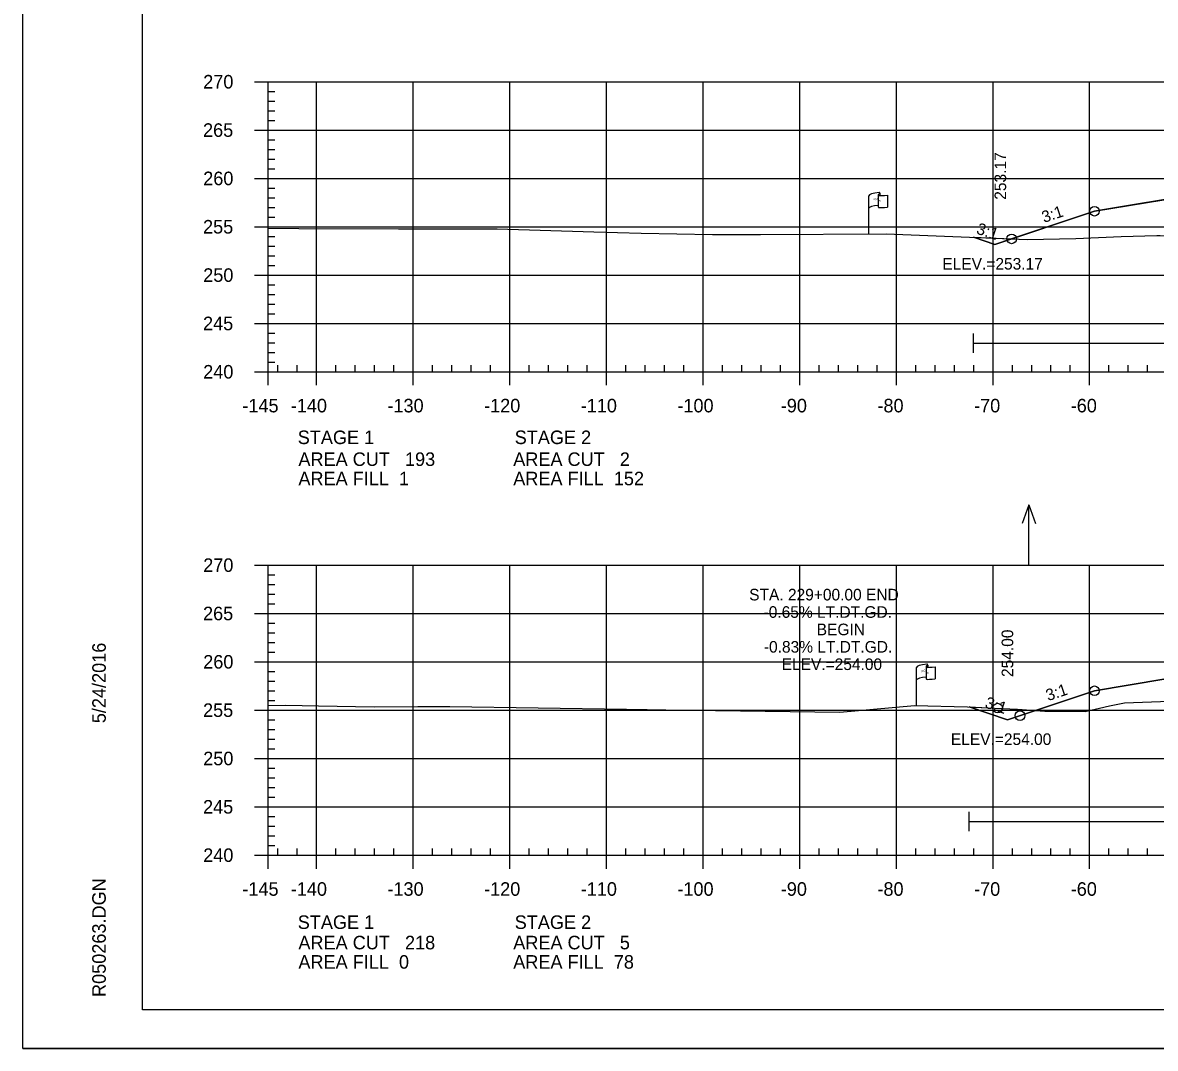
# Model space of a CAD drawing. Extents: x 1365647 to 1367999, y 387113 to 400173.
# Drawn here: x 1365723.7 to 1365840.9, y 392066.2 to 392172.3 of the extents above; entities that cross this region are included whole.
import ezdxf

# ---------------------------------------------------------------- set-up
doc = ezdxf.new("R2010")
doc.units = 0
for name, color, linetype in [('E_Existing ROW', 7, 'Continuous'), ('R_Axis', 7, 'Continuous'), ('R_Axis Annot', 7, 'Continuous'), ('R_Border', 7, 'Continuous'), ('R_Border Notes', 7, 'Continuous'), ('R_Contours', 7, 'Continuous'), ('R_Exist Surface', 7, 'Continuous'), ('R_Fin Surface', 7, 'Continuous'), ('R_Fin Surface Annot', 7, 'Continuous'), ('R_Grid', 7, 'Continuous'), ('R_No Plot', 7, 'Continuous'), ('R_Proposed Const Limits', 7, 'Continuous'), ('R_Water', 7, 'Continuous'), ('R_Water Annot', 7, 'Continuous')]:
    doc.layers.add(name, color=color, linetype=linetype)

msp = doc.modelspace()

# ---------------------------------------------------------------- linework, layer by layer
at = {"layer": 'E_Existing ROW'}
for p, q in [((1365811.23, 392150.41), (1365811.23, 392154.36)), ((1365812.22, 392154.45), (1365812.22, 392154.44)), ((1365812.22, 392154.44), (1365812.22, 392153.21)), ((1365812.39, 392154.61), (1365812.39, 392154.37)), ((1365813.16, 392154.41), (1365813.16, 392153.17)), ((1365817.17, 392105.66), (1365817.17, 392105.65)), ((1365817.17, 392105.65), (1365817.17, 392104.42)), ((1365817.34, 392105.82), (1365817.34, 392105.58)), ((1365818.1, 392105.62), (1365818.1, 392104.38)), ((1365816.17, 392101.62), (1365816.17, 392105.57))]:
    msp.add_line(p, q, dxfattribs=at)
for centre, radius, start, end in [((1365812.3, 392154.45), 0.078, 88.6458, 274.2828), ((1365812.31, 392154.61), 0.0783, 263.0712, 93.9564), ((1365812.3, 392153.21), 0.0783, 180, 273.9564), ((1365817.25, 392105.66), 0.078, 88.6458, 274.2828), ((1365817.26, 392105.82), 0.0783, 263.0712, 93.9564), ((1365817.25, 392104.42), 0.0783, 180, 273.9564)]:
    msp.add_arc(centre, radius, start, end, dxfattribs=at)
for centre, major_axis, ratio, start_param, end_param in [((1365812.81, 392154.4), (-1.58, -0.04), 0.19887, 5.030368, 6.283185), ((1365813.52, 392154.52), (-1.23, -0.13), 0.052933, 0.159456, 1.268315), ((1365812.8, 392153.08), (-1.58, -0.04), 0.19887, 5.083035, 6.194897), ((1365813.52, 392153.28), (-1.23, -0.13), 0.052933, 0.159456, 1.268315), ((1365817.75, 392105.61), (-1.58, -0.04), 0.19887, 5.030368, 6.283185), ((1365818.46, 392105.72), (-1.23, -0.13), 0.052933, 0.159456, 1.268315), ((1365817.75, 392104.29), (-1.58, -0.04), 0.19887, 5.083035, 6.194897), ((1365818.46, 392104.48), (-1.23, -0.13), 0.052933, 0.159456, 1.268315)]:
    msp.add_ellipse(centre, major_axis=major_axis, ratio=ratio, start_param=start_param, end_param=end_param, dxfattribs=at)
at = {"layer": 'R_Axis'}
for p, q in [((1365747.69, 392166.15), (1365749.09, 392166.15)), ((1365749.09, 392136.15), (1365749.09, 392166.15)), ((1365749.09, 392165.15), (1365749.79, 392165.15)), ((1365749.09, 392164.15), (1365749.79, 392164.15)), ((1365749.09, 392163.15), (1365749.79, 392163.15)), ((1365749.09, 392162.15), (1365749.79, 392162.15)), ((1365747.69, 392161.15), (1365749.09, 392161.15)), ((1365749.09, 392160.15), (1365749.79, 392160.15)), ((1365749.09, 392159.15), (1365749.79, 392159.15)), ((1365749.09, 392158.15), (1365749.79, 392158.15)), ((1365747.69, 392156.15), (1365749.09, 392156.15)), ((1365749.09, 392157.15), (1365749.79, 392157.15)), ((1365749.09, 392155.15), (1365749.79, 392155.15)), ((1365749.09, 392154.15), (1365749.79, 392154.15)), ((1365749.09, 392153.15), (1365749.79, 392153.15)), ((1365749.09, 392152.15), (1365749.79, 392152.15)), ((1365747.69, 392151.15), (1365749.09, 392151.15)), ((1365749.09, 392150.15), (1365749.79, 392150.15)), ((1365749.09, 392149.15), (1365749.79, 392149.15)), ((1365749.09, 392148.15), (1365749.79, 392148.15)), ((1365749.09, 392147.15), (1365749.79, 392147.15)), ((1365747.69, 392146.15), (1365749.09, 392146.15)), ((1365749.09, 392145.15), (1365749.79, 392145.15)), ((1365749.09, 392144.15), (1365749.79, 392144.15)), ((1365749.09, 392143.15), (1365749.79, 392143.15)), ((1365749.09, 392142.15), (1365749.79, 392142.15)), ((1365747.69, 392141.15), (1365749.09, 392141.15)), ((1365749.09, 392140.15), (1365749.79, 392140.15)), ((1365749.09, 392139.15), (1365749.79, 392139.15)), ((1365749.09, 392138.15), (1365749.79, 392138.15)), ((1365747.69, 392136.15), (1365749.09, 392136.15)), ((1365749.09, 392137.15), (1365749.79, 392137.15)), ((1365749.09, 392136.15), (1365749.09, 392136.85)), ((1365749.09, 392136.15), (1366039.09, 392136.15)), ((1365749.09, 392134.75), (1365749.09, 392136.15)), ((1365750.09, 392136.15), (1365750.09, 392136.85)), ((1365752.09, 392136.15), (1365752.09, 392136.85)), ((1365754.09, 392134.75), (1365754.09, 392136.15)), ((1365756.09, 392136.15), (1365756.09, 392136.85)), ((1365758.09, 392136.15), (1365758.09, 392136.85)), ((1365760.09, 392136.15), (1365760.09, 392136.85)), ((1365762.09, 392136.15), (1365762.09, 392136.85)), ((1365764.09, 392134.75), (1365764.09, 392136.15)), ((1365766.09, 392136.15), (1365766.09, 392136.85)), ((1365768.09, 392136.15), (1365768.09, 392136.85)), ((1365770.09, 392136.15), (1365770.09, 392136.85)), ((1365772.09, 392136.15), (1365772.09, 392136.85)), ((1365774.09, 392134.75), (1365774.09, 392136.15)), ((1365776.09, 392136.15), (1365776.09, 392136.85)), ((1365778.09, 392136.15), (1365778.09, 392136.85)), ((1365780.09, 392136.15), (1365780.09, 392136.85)), ((1365782.09, 392136.15), (1365782.09, 392136.85)), ((1365784.09, 392134.75), (1365784.09, 392136.15)), ((1365786.09, 392136.15), (1365786.09, 392136.85)), ((1365788.09, 392136.15), (1365788.09, 392136.85)), ((1365790.09, 392136.15), (1365790.09, 392136.85)), ((1365792.09, 392136.15), (1365792.09, 392136.85)), ((1365794.09, 392134.75), (1365794.09, 392136.15)), ((1365796.09, 392136.15), (1365796.09, 392136.85)), ((1365798.09, 392136.15), (1365798.09, 392136.85)), ((1365800.09, 392136.15), (1365800.09, 392136.85)), ((1365802.09, 392136.15), (1365802.09, 392136.85)), ((1365804.09, 392134.75), (1365804.09, 392136.15)), ((1365806.09, 392136.15), (1365806.09, 392136.85)), ((1365808.09, 392136.15), (1365808.09, 392136.85)), ((1365810.09, 392136.15), (1365810.09, 392136.85)), ((1365812.09, 392136.15), (1365812.09, 392136.85)), ((1365814.09, 392134.75), (1365814.09, 392136.15)), ((1365816.09, 392136.15), (1365816.09, 392136.85)), ((1365818.09, 392136.15), (1365818.09, 392136.85)), ((1365820.09, 392136.15), (1365820.09, 392136.85)), ((1365822.09, 392136.15), (1365822.09, 392136.85)), ((1365824.09, 392134.75), (1365824.09, 392136.15)), ((1365826.09, 392136.15), (1365826.09, 392136.85)), ((1365828.09, 392136.15), (1365828.09, 392136.85)), ((1365830.09, 392136.15), (1365830.09, 392136.85)), ((1365832.09, 392136.15), (1365832.09, 392136.85)), ((1365834.09, 392134.75), (1365834.09, 392136.15)), ((1365836.09, 392136.15), (1365836.09, 392136.85)), ((1365838.09, 392136.15), (1365838.09, 392136.85)), ((1365840.09, 392136.15), (1365840.09, 392136.85)), ((1365747.69, 392116.15), (1365749.09, 392116.15)), ((1365749.09, 392086.15), (1365749.09, 392116.15)), ((1365749.09, 392115.15), (1365749.79, 392115.15)), ((1365749.09, 392114.15), (1365749.79, 392114.15)), ((1365749.09, 392113.15), (1365749.79, 392113.15)), ((1365749.09, 392112.15), (1365749.79, 392112.15)), ((1365747.69, 392111.15), (1365749.09, 392111.15)), ((1365749.09, 392110.15), (1365749.79, 392110.15)), ((1365749.09, 392109.15), (1365749.79, 392109.15)), ((1365749.09, 392108.15), (1365749.79, 392108.15)), ((1365749.09, 392107.15), (1365749.79, 392107.15)), ((1365747.69, 392106.15), (1365749.09, 392106.15)), ((1365749.09, 392105.15), (1365749.79, 392105.15)), ((1365749.09, 392104.15), (1365749.79, 392104.15)), ((1365749.09, 392103.15), (1365749.79, 392103.15)), ((1365749.09, 392102.15), (1365749.79, 392102.15)), ((1365747.69, 392101.15), (1365749.09, 392101.15)), ((1365749.09, 392100.15), (1365749.79, 392100.15)), ((1365749.09, 392099.15), (1365749.79, 392099.15)), ((1365749.09, 392098.15), (1365749.79, 392098.15)), ((1365749.09, 392097.15), (1365749.79, 392097.15)), ((1365747.69, 392096.15), (1365749.09, 392096.15)), ((1365749.09, 392095.15), (1365749.79, 392095.15)), ((1365749.09, 392094.15), (1365749.79, 392094.15)), ((1365749.09, 392093.15), (1365749.79, 392093.15)), ((1365749.09, 392092.15), (1365749.79, 392092.15)), ((1365747.69, 392091.15), (1365749.09, 392091.15)), ((1365749.09, 392090.15), (1365749.79, 392090.15)), ((1365749.09, 392089.15), (1365749.79, 392089.15)), ((1365749.09, 392088.15), (1365749.79, 392088.15)), ((1365749.09, 392087.15), (1365749.79, 392087.15)), ((1365749.09, 392086.15), (1365749.09, 392086.85)), ((1365750.09, 392086.15), (1365750.09, 392086.85)), ((1365752.09, 392086.15), (1365752.09, 392086.85)), ((1365756.09, 392086.15), (1365756.09, 392086.85)), ((1365758.09, 392086.15), (1365758.09, 392086.85)), ((1365760.09, 392086.15), (1365760.09, 392086.85)), ((1365762.09, 392086.15), (1365762.09, 392086.85)), ((1365766.09, 392086.15), (1365766.09, 392086.85)), ((1365768.09, 392086.15), (1365768.09, 392086.85)), ((1365770.09, 392086.15), (1365770.09, 392086.85)), ((1365772.09, 392086.15), (1365772.09, 392086.85)), ((1365776.09, 392086.15), (1365776.09, 392086.85)), ((1365778.09, 392086.15), (1365778.09, 392086.85)), ((1365780.09, 392086.15), (1365780.09, 392086.85)), ((1365782.09, 392086.15), (1365782.09, 392086.85)), ((1365786.09, 392086.15), (1365786.09, 392086.85)), ((1365788.09, 392086.15), (1365788.09, 392086.85)), ((1365790.09, 392086.15), (1365790.09, 392086.85)), ((1365792.09, 392086.15), (1365792.09, 392086.85)), ((1365796.09, 392086.15), (1365796.09, 392086.85)), ((1365798.09, 392086.15), (1365798.09, 392086.85)), ((1365800.09, 392086.15), (1365800.09, 392086.85)), ((1365802.09, 392086.15), (1365802.09, 392086.85)), ((1365806.09, 392086.15), (1365806.09, 392086.85)), ((1365808.09, 392086.15), (1365808.09, 392086.85)), ((1365810.09, 392086.15), (1365810.09, 392086.85)), ((1365812.09, 392086.15), (1365812.09, 392086.85)), ((1365816.09, 392086.15), (1365816.09, 392086.85)), ((1365818.09, 392086.15), (1365818.09, 392086.85)), ((1365820.09, 392086.15), (1365820.09, 392086.85)), ((1365822.09, 392086.15), (1365822.09, 392086.85)), ((1365826.09, 392086.15), (1365826.09, 392086.85)), ((1365828.09, 392086.15), (1365828.09, 392086.85)), ((1365830.09, 392086.15), (1365830.09, 392086.85)), ((1365832.09, 392086.15), (1365832.09, 392086.85)), ((1365836.09, 392086.15), (1365836.09, 392086.85)), ((1365838.09, 392086.15), (1365838.09, 392086.85)), ((1365840.09, 392086.15), (1365840.09, 392086.85)), ((1365747.69, 392086.15), (1365749.09, 392086.15)), ((1365749.09, 392086.15), (1366039.09, 392086.15)), ((1365749.09, 392084.75), (1365749.09, 392086.15)), ((1365754.09, 392084.75), (1365754.09, 392086.15)), ((1365764.09, 392084.75), (1365764.09, 392086.15)), ((1365774.09, 392084.75), (1365774.09, 392086.15)), ((1365784.09, 392084.75), (1365784.09, 392086.15)), ((1365794.09, 392084.75), (1365794.09, 392086.15)), ((1365804.09, 392084.75), (1365804.09, 392086.15)), ((1365814.09, 392084.75), (1365814.09, 392086.15)), ((1365824.09, 392084.75), (1365824.09, 392086.15)), ((1365834.09, 392084.75), (1365834.09, 392086.15))]:
    msp.add_line(p, q, dxfattribs=at)
at = {"layer": 'R_Border'}
for p, q in [((1365736.09, 392070.15), (1365736.09, 392275.61)), ((1365736.09, 392070.15), (1365736.09, 392070.15)), ((1366052.27, 392070.15), (1365736.09, 392070.15))]:
    msp.add_line(p, q, dxfattribs=at)
at = {"layer": 'R_Contours'}
for points in [[(1365826.02, 392149.9), (1365827.63, 392149.83), (1365832.67, 392149.94), (1365837.35, 392150.14), (1365841.05, 392150.23), (1365841.37, 392150.24), (1365841.82, 392150.21), (1365843.13, 392150.26), (1365847.8, 392150.36), (1365850.89, 392150.1), (1365854.19, 392149.57), (1365855.74, 392149.49), (1365857.79, 392149.47), (1365861.92, 392150.42), (1365866.14, 392151.44), (1365868.16, 392151.62), (1365870.56, 392151.81), (1365878.39, 392152.3), (1365880.93, 392152.49), (1365881.43, 392152.53), (1365862.59, 392154.37), (1365841.78, 392153.95), (1365834.59, 392152.76)], [(1365822.07, 392150.06), (1365826.02, 392149.9), (1365824.28, 392149.32)], [(1365828.5, 392101.12), (1365829.46, 392101.05), (1365830.69, 392101.03), (1365833.61, 392101.02), (1365836.13, 392101.59), (1365837.68, 392101.9), (1365852.59, 392102.46), (1365857.6, 392102.66), (1365861.83, 392102.82), (1365866.23, 392102.96), (1365870.84, 392103.26), (1365871.68, 392103.22), (1365873.07, 392103.35), (1365876.85, 392103.25), (1365877.76, 392103.23), (1365878.2, 392103.24), (1365862.59, 392104.76), (1365841.78, 392104.35), (1365834.59, 392103.15)], [(1365821.63, 392101.48), (1365824.25, 392101.37), (1365826.63, 392101.26), (1365828.5, 392101.12), (1365825.6, 392100.15)]]:
    msp.add_lwpolyline(points, close=True, dxfattribs=at)
at = {"layer": 'R_Exist Surface'}
for points in [[(1365749.09, 392150.99), (1365752.25, 392150.96), (1365762.57, 392150.95), (1365772.78, 392150.95), (1365782.8, 392150.62), (1365787.7, 392150.48), (1365795.06, 392150.36), (1365795.72, 392150.35), (1365800.04, 392150.36), (1365813.05, 392150.41), (1365820.79, 392150.11), (1365827.63, 392149.83), (1365832.67, 392149.94), (1365837.35, 392150.14), (1365841.05, 392150.23)], [(1365749.09, 392101.62), (1365750.93, 392101.67), (1365754.29, 392101.6), (1365760.05, 392101.51), (1365764.58, 392101.52), (1365767.9, 392101.52), (1365786.18, 392101.26), (1365788.31, 392101.23), (1365790.23, 392101.2), (1365808.23, 392100.94), (1365811.71, 392101.25), (1365815.95, 392101.62), (1365821.45, 392101.48), (1365824.25, 392101.37), (1365826.63, 392101.26), (1365829.46, 392101.05), (1365830.69, 392101.03), (1365833.61, 392101.02), (1365836.13, 392101.59), (1365837.68, 392101.9), (1365852.59, 392102.46)]]:
    msp.add_lwpolyline(points, dxfattribs=at)
at = {"layer": 'R_Fin Surface'}
for points in [[(1365822.07, 392150.06), (1365824.28, 392149.32), (1365834.59, 392152.76), (1365841.78, 392153.95), (1365856.59, 392156.42), (1365862.59, 392155.83), (1365864.59, 392155.64), (1365894.09, 392152.75), (1365923.59, 392149.86), (1365925.59, 392149.66), (1365931.59, 392149.07), (1365953.01, 392145.5), (1365953.59, 392145.41), (1365956.77, 392144.35), (1365980, 392152.09)], [(1365821.63, 392101.48), (1365825.6, 392100.15), (1365834.59, 392103.15), (1365841.78, 392104.35), (1365856.59, 392106.82), (1365862.59, 392106.23), (1365864.59, 392106.03), (1365894.09, 392103.14), (1365923.59, 392100.25), (1365925.59, 392100.05), (1365931.59, 392099.47), (1365953.01, 392095.9), (1365953.59, 392095.8), (1365957.39, 392094.53), (1365980.9, 392102.37)]]:
    msp.add_lwpolyline(points, dxfattribs=at)
at = {"layer": 'R_Grid'}
for p, q in [((1365749.09, 392166.15), (1366039.09, 392166.15)), ((1365749.09, 392136.15), (1365749.09, 392166.15)), ((1365754.09, 392136.15), (1365754.09, 392166.15)), ((1365764.09, 392136.15), (1365764.09, 392166.15)), ((1365774.09, 392136.15), (1365774.09, 392166.15)), ((1365784.09, 392136.15), (1365784.09, 392166.15)), ((1365794.09, 392136.15), (1365794.09, 392166.15)), ((1365804.09, 392136.15), (1365804.09, 392166.15)), ((1365814.09, 392136.15), (1365814.09, 392166.15)), ((1365824.09, 392136.15), (1365824.09, 392166.15)), ((1365834.09, 392136.15), (1365834.09, 392166.15)), ((1365749.09, 392161.15), (1366039.09, 392161.15)), ((1365749.09, 392156.15), (1366039.09, 392156.15)), ((1365749.09, 392151.15), (1366039.09, 392151.15)), ((1365749.09, 392146.15), (1366039.09, 392146.15)), ((1365749.09, 392141.15), (1366039.09, 392141.15)), ((1365749.09, 392136.15), (1366039.09, 392136.15)), ((1365749.09, 392116.15), (1366039.09, 392116.15)), ((1365749.09, 392086.15), (1365749.09, 392116.15)), ((1365754.09, 392086.15), (1365754.09, 392116.15)), ((1365764.09, 392086.15), (1365764.09, 392116.15)), ((1365774.09, 392086.15), (1365774.09, 392116.15)), ((1365784.09, 392086.15), (1365784.09, 392116.15)), ((1365794.09, 392086.15), (1365794.09, 392116.15)), ((1365804.09, 392086.15), (1365804.09, 392116.15)), ((1365814.09, 392086.15), (1365814.09, 392116.15)), ((1365824.09, 392086.15), (1365824.09, 392116.15)), ((1365834.09, 392086.15), (1365834.09, 392116.15)), ((1365749.09, 392111.15), (1366039.09, 392111.15)), ((1365749.09, 392106.15), (1366039.09, 392106.15)), ((1365749.09, 392101.15), (1366039.09, 392101.15)), ((1365749.09, 392096.15), (1366039.09, 392096.15)), ((1365749.09, 392091.15), (1366039.09, 392091.15)), ((1365749.09, 392086.15), (1366039.09, 392086.15))]:
    msp.add_line(p, q, dxfattribs=at)
at = {"layer": 'R_No Plot'}
msp.add_line((1365723.69, 392066.17), (1366057.03, 392066.17), dxfattribs=at)
msp.add_lwpolyline([(1365723.69, 392279.51), (1366057.03, 392279.51), (1366057.03, 392066.17), (1365723.69, 392066.17)], close=True, dxfattribs=at)
for centre in [(1365834.59, 392152.76), (1365834.59, 392152.76), (1365834.59, 392152.76), (1365834.59, 392152.76), (1365834.59, 392152.76), (1365826.02, 392149.9), (1365826.02, 392149.9), (1365834.59, 392103.15), (1365834.59, 392103.15), (1365834.59, 392103.15), (1365834.59, 392103.15), (1365834.59, 392103.15), (1365824.57, 392101.36), (1365824.57, 392101.36), (1365826.89, 392100.58), (1365826.89, 392100.58)]:
    msp.add_circle(centre, 0.5, dxfattribs=at)
at = {"layer": 'R_Proposed Const Limits'}
msp.add_lwpolyline([(1365856.59, 392156.42), (1365834.59, 392152.76), (1365826.02, 392149.9)], dxfattribs=at)
at = {"layer": 'R_Water'}
for p, q in [((1365822.07, 392138.11), (1365822.07, 392140.11)), ((1365822.07, 392139.11), (1365883.9, 392139.11)), ((1365821.63, 392088.64), (1365821.63, 392090.64)), ((1365821.63, 392089.64), (1365882.95, 392089.64))]:
    msp.add_line(p, q, dxfattribs=at)
at = {"layer": 'R_Water Annot'}
for p, q in [((1365827.8, 392122.37), (1365827.1, 392120.45)), ((1365827.8, 392116.09), (1365827.8, 392122.37)), ((1365827.8, 392122.37), (1365828.5, 392120.45))]:
    msp.add_line(p, q, dxfattribs=at)

# ---------------------------------------------------------------- texts
at = {"layer": 'E_Existing ROW'}
for s, height, rotation, p in [('R ', 0.2, 9.9884, (1365811.75, 392153.86)), (' O', 0.2, 9.9884, (1365811.89, 392153.9)), ('W', 0.2, 351.1788, (1365812.22, 392153.74)), ('DWB 11-9-07', 0.001, 90, (1365812.39, 392154.37)), ('DWB 11-9-07', 0.001, 5.0717, (1365813.15, 392153.17)), ('DWB 11-9-07', 0.001, 90, (1365811.23, 392150.41)), ('R ', 0.2, 9.9884, (1365816.69, 392105.07)), (' O', 0.2, 9.9884, (1365816.84, 392105.11)), ('W', 0.2, 351.1788, (1365817.17, 392104.94)), ('DWB 11-9-07', 0.001, 90, (1365817.33, 392105.58)), ('DWB 11-9-07', 0.001, 5.0717, (1365818.09, 392104.38)), ('DWB 11-9-07', 0.001, 90, (1365816.17, 392101.62))]:
    msp.add_text(s, height=height, rotation=rotation, dxfattribs=at).set_placement(p)
at = {"layer": 'R_Axis Annot'}
for s, p in [('270', (1365742.37, 392165.45)), ('265', (1365742.35, 392160.45)), ('260', (1365742.37, 392155.45)), ('255', (1365742.35, 392150.45)), ('250', (1365742.37, 392145.45)), ('245', (1365742.35, 392140.45)), ('240', (1365742.37, 392135.45)), ('-145', (1365746.42, 392131.95)), ('-140', (1365751.43, 392131.95)), ('-130', (1365761.43, 392131.95)), ('-120', (1365771.43, 392131.95)), ('-110', (1365781.43, 392131.95)), ('-100', (1365791.43, 392131.95)), ('-90', (1365802.13, 392131.95)), ('-80', (1365812.13, 392131.95)), ('-70', (1365822.13, 392131.95)), ('-60', (1365832.13, 392131.95)), ('STAGE 1', (1365752.15, 392128.67)), ('STAGE 2', (1365774.6, 392128.67)), ('AREA CUT   193', (1365752.22, 392126.41)), ('AREA CUT   2', (1365774.45, 392126.41)), ('AREA FILL  1', (1365752.22, 392124.41)), ('AREA FILL  152', (1365774.45, 392124.41)), ('270', (1365742.37, 392115.45)), ('265', (1365742.35, 392110.45)), ('260', (1365742.37, 392105.45)), ('255', (1365742.35, 392100.45)), ('250', (1365742.37, 392095.45)), ('245', (1365742.35, 392090.45)), ('240', (1365742.37, 392085.45)), ('-145', (1365746.42, 392081.95)), ('-140', (1365751.43, 392081.95)), ('-130', (1365761.43, 392081.95)), ('-120', (1365771.43, 392081.95)), ('-110', (1365781.43, 392081.95)), ('-100', (1365791.43, 392081.95)), ('-90', (1365802.13, 392081.95)), ('-80', (1365812.13, 392081.95)), ('-70', (1365822.13, 392081.95)), ('-60', (1365832.13, 392081.95)), ('STAGE 1', (1365752.15, 392078.52)), ('STAGE 2', (1365774.6, 392078.52)), ('AREA CUT   218', (1365752.22, 392076.41)), ('AREA CUT   5', (1365774.45, 392076.41)), ('AREA FILL  0', (1365752.22, 392074.41)), ('AREA FILL  78', (1365774.45, 392074.41))]:
    msp.add_text(s, height=1.4, dxfattribs=at).set_placement(p)
at = {"layer": 'R_Border'}
for s, p in [('5/24/2016', (1365732.29, 392099.8)), ('R050263.DGN', (1365732.29, 392071.48))]:
    msp.add_text(s, height=1.4, rotation=90, dxfattribs=at).set_placement(p)
at = {"layer": 'R_Border Notes'}
for s, p in [('ELEV.=253.17', (1365818.85, 392146.72)), ('ELEV.=254.00', (1365819.73, 392097.55))]:
    msp.add_text(s, height=1.2, dxfattribs=at).set_placement(p)
at = {"layer": 'R_Fin Surface Annot'}
for s, rotation, p in [('253.17', 90, (1365825.45, 392153.94)), ('3:1', 18.4349, (1365829.36, 392151.54)), ('3:1', 341.5651, (1365822.29, 392150.46)), ('254.00', 90, (1365826.18, 392104.58)), ('3:1', 18.4349, (1365829.79, 392102.08)), ('3:1', 341.5651, (1365823.17, 392101.44))]:
    msp.add_text(s, height=1.2, rotation=rotation, dxfattribs=at).set_placement(p)
at = {"layer": 'R_Water'}
for s, p in [('STA. 229+00.00 END', (1365798.86, 392112.5)), ('-0.65% LT.DT.GD.', (1365800.35, 392110.7)), ('BEGIN', (1365805.85, 392108.9)), ('-0.83% LT.DT.GD.', (1365800.38, 392107.1)), ('ELEV.=254.00', (1365802.22, 392105.3))]:
    msp.add_text(s, height=1.2, dxfattribs=at).set_placement(p)

doc.saveas('drawing.dxf')
